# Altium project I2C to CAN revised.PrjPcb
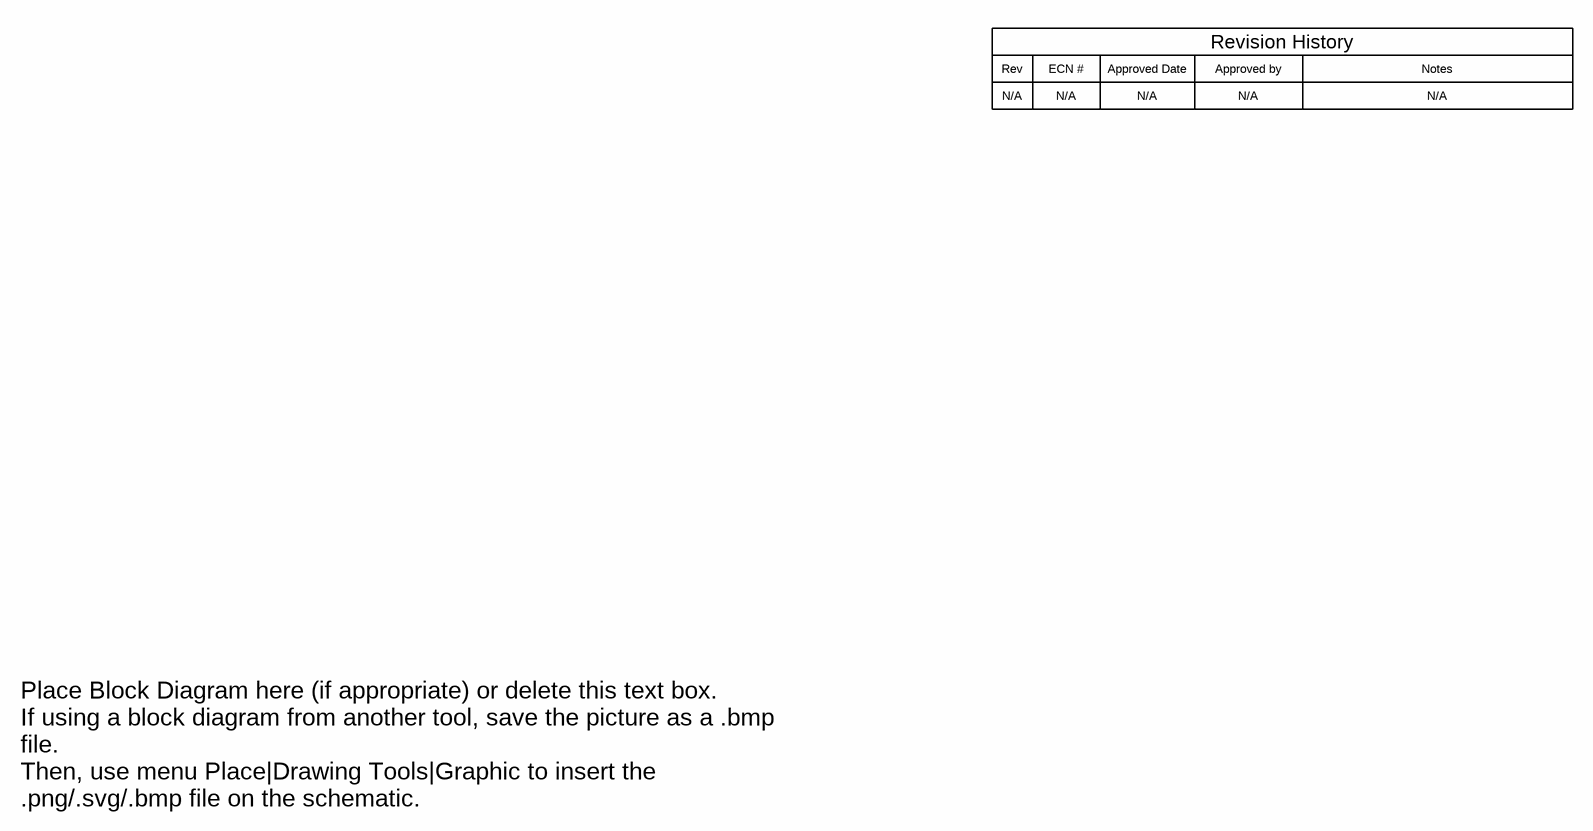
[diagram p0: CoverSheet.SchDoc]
CopyrightYear: 2017; PCB_Layout: Who did the Layout?; PCB_Rev: E1; PRJ_Customer: Public Release; PRJ_Engineer: Enter name of project lead; PRJ_Number: XX####; PRJ_Title: Change in menu Project|Project Options|Parameters; SCH_Rev: E1; TechSupport: http://www.ti.com/support; TID: N/A
3 sheets, 56 parts. Net scope: global (net labels, ports and power ports of the same name join across sheets).
Board file: I2C to CAN 2018.PcbDoc
Sheets:
  CoverSheet.SchDoc
  I2C to CAN 2018.SchDoc
  EVM_Hardware.SchDoc

## Sheet CoverSheet.SchDoc
size 431 x 279 mm; Date: Not shown in title block; ApprovedBy: Not shown in title block; CheckedBy: Not shown in title block; Author: Not shown in title block; CompanyName: Not shown in title block; Engineer: Not shown in title block; Organization: Not shown in title block; Address1: Not shown in title block; Address2: Not shown in title block; Address3: Not shown in title block; Address4: Not shown in title block; DocumentNumber: 1; Revision: Use project parameter SCH_Rev; SheetNumber: 1; SheetTotal: 3; PageSetup: Record=PageOptions¦CenterHorizontal=True¦CenterVertical=True¦PrintScale=1.00¦XCorrection=1.00¦YCorrection=1.00¦PrintKind=0¦BorderSize=5000000¦LeftOffset=0¦BottomOffset=0¦Orientation=2¦PaperLength=1000¦PaperWidth=1000¦Scale=100¦PaperSource=15¦PrintQuality=600¦MediaType=1¦DitherType=10¦PaperKind=Letter¦PrintScaleMode=1

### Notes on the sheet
- Rev
- N/A
- ECN #
- Approved Date
- Approved by
- Revision History
- Notes
- Place Block Diagram here (if appropriate) or delete this text box.
  If using a block diagram from another tool, save the picture as a .bmp file.
  Then, use menu Place|Drawing Tools|Graphic to insert the .png/.svg/.bmp file on the schematic.

## Sheet I2C to CAN 2018.SchDoc
size 431 x 279 mm; Date: Not shown in title block; ApprovedBy: Not shown in title block; CheckedBy: Not shown in title block; Author: Not shown in title block; CompanyName: Not shown in title block; Engineer: Not shown in title block; Organization: Not shown in title block; Address1: Not shown in title block; Address2: Not shown in title block; Address3: Not shown in title block; Address4: Not shown in title block; DocumentNumber: 1; Revision: Use project parameter SCH_Rev; SheetNumber: 2; SheetTotal: 3; PageSetup: Record=PageOptions¦CenterHorizontal=True¦CenterVertical=True¦PrintScale=1.00¦XCorrection=1.00¦YCorrection=1.00¦PrintKind=0¦BorderSize=5000000¦LeftOffset=0¦BottomOffset=0¦Orientation=2¦PaperLength=1000¦PaperWidth=1000¦Scale=100¦PaperSource=15¦PrintQuality=600¦MediaType=1¦DitherType=10¦PaperKind=Letter¦PrintScaleMode=1
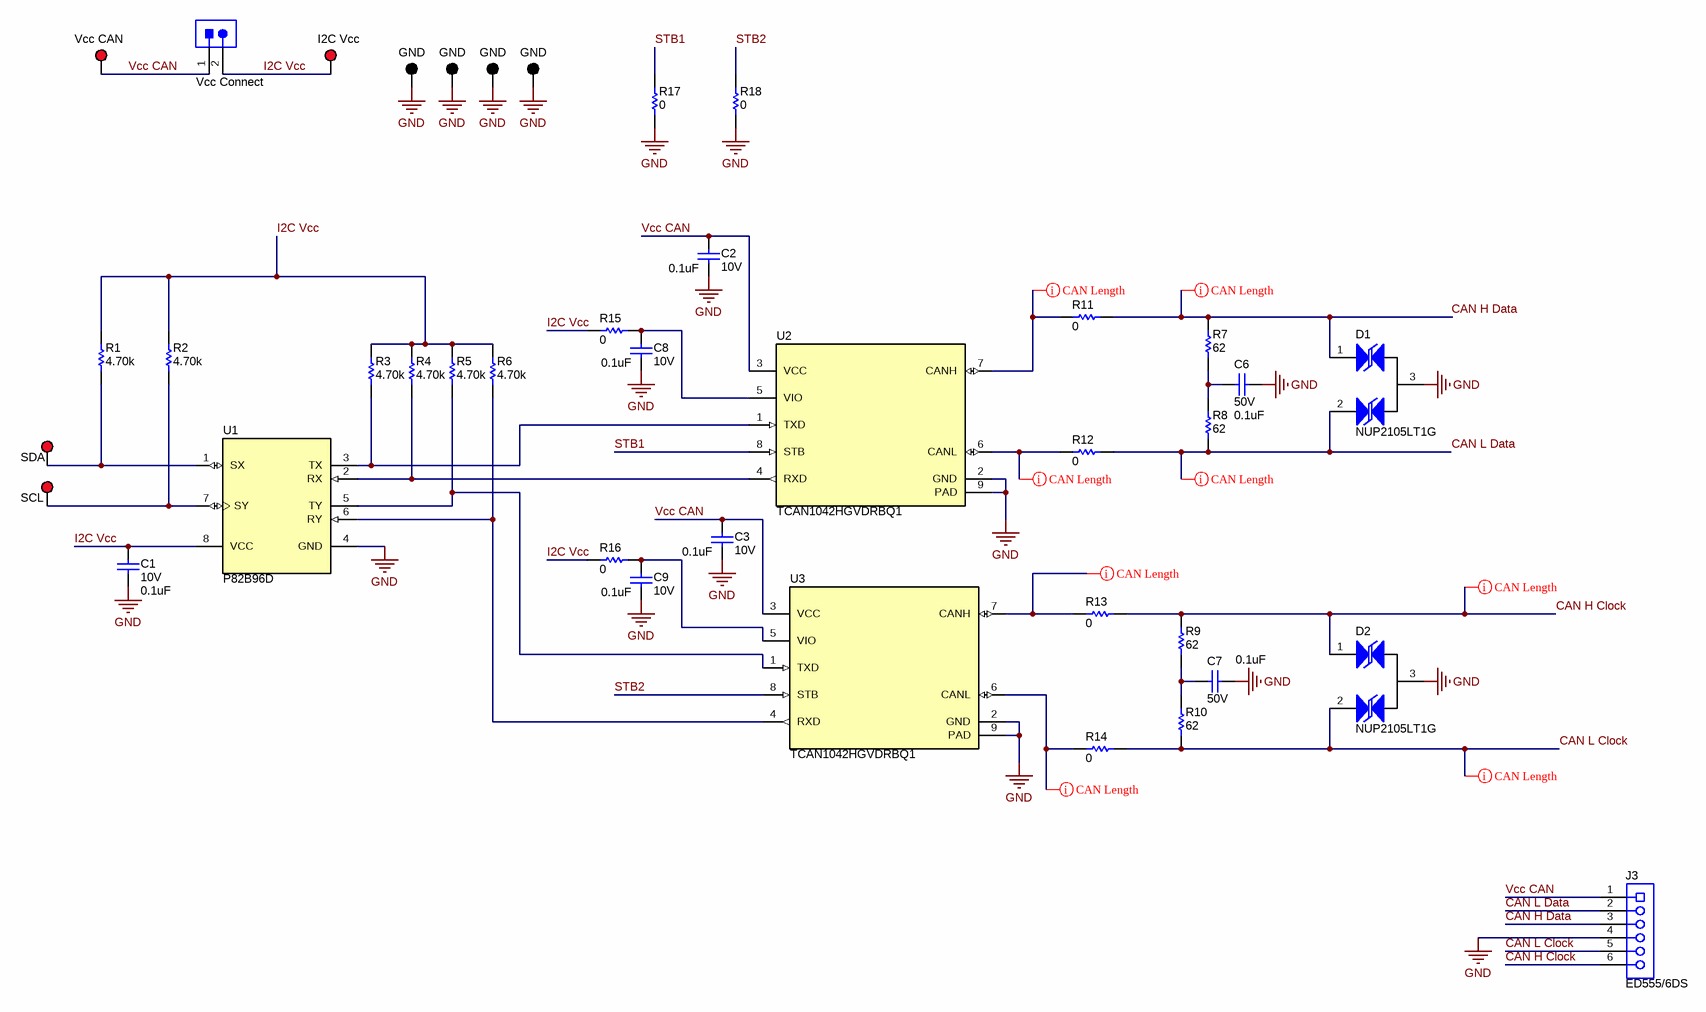
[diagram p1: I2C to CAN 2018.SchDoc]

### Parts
C1  VDC_V: 10V  ValueDisplayed: 0.1uF  [0603]  (hidden comment: 885012206020)
C2  VDC_V: 10V  ValueDisplayed: 0.1uF  [0603]  (hidden comment: 885012206020)
C3  VDC_V: 10V  ValueDisplayed: 0.1uF  [0603]  (hidden comment: 885012206020)
C6  VDC_V: 50V  ValueDisplayed: 0.1uF  [0603]  (hidden comment: C1608X5R1H104K080AA)
C7  VDC_V: 50V  ValueDisplayed: 0.1uF  [0603]  (hidden comment: C1608X5R1H104K080AA)
C8  VDC_V: 10V  ValueDisplayed: 0.1uF  [0603]  (hidden comment: 885012206020)
C9  VDC_V: 10V  ValueDisplayed: 0.1uF  [0603]  (hidden comment: 885012206020)
D1  NUP2105LT1G  [SOT-23]
D2  NUP2105LT1G  [SOT-23]
J3  ED555/6DS  [TERM_BLK_ED555-6DS]
J4  Vcc Connect  [3M_961102-6404-AR]
R1  ValueDisplayed: 4.70k  [0603]  (hidden comment: RT0603BRD074K7L)
R2  ValueDisplayed: 4.70k  [0603]  (hidden comment: RT0603BRD074K7L)
R3  ValueDisplayed: 4.70k  [0603]  (hidden comment: RT0603BRD074K7L)
R4  ValueDisplayed: 4.70k  [0603]  (hidden comment: RT0603BRD074K7L)
R5  ValueDisplayed: 4.70k  [0603]  (hidden comment: RT0603BRD074K7L)
R6  ValueDisplayed: 4.70k  [0603]  (hidden comment: RT0603BRD074K7L)
R7  ValueDisplayed: 62  [0603]  (hidden comment: CRCW060362R0JNEA)
R8  ValueDisplayed: 62  [0603]  (hidden comment: CRCW060362R0JNEA)
R9  ValueDisplayed: 62  [0603]  (hidden comment: CRCW060362R0JNEA)
R10  ValueDisplayed: 62  [0603]  (hidden comment: CRCW060362R0JNEA)
R11  ValueDisplayed: 0  [1210]  (hidden comment: CRCW12100000Z0EA)
R12  ValueDisplayed: 0  [1210]  (hidden comment: CRCW12100000Z0EA)
R13  ValueDisplayed: 0  [1210]  (hidden comment: CRCW12100000Z0EA)
R14  ValueDisplayed: 0  [1210]  (hidden comment: CRCW12100000Z0EA)
R15  ValueDisplayed: 0  [0603]  (hidden comment: RT0603BRD074K7L)
R16  ValueDisplayed: 0  [0603]  (hidden comment: RT0603BRD074K7L)
R17  ValueDisplayed: 0  [0603]  (hidden comment: RT0603BRD074K7L)
R18  ValueDisplayed: 0  [0603]  (hidden comment: RT0603BRD074K7L)
TP1  I2C Vcc  [Keystone5010]
TP2  Vcc CAN  [Keystone5010]
TP3  GND  [Keystone5011]
TP4  GND  [Keystone5011]
TP5  GND  [Keystone5011]
TP6  GND  [Keystone5011]
TP7  SDA  [Keystone5010]
TP8  SCL  [Keystone5010]
U1  P82B96D  [D0008A_L]
U2  TCAN1042HGVDRBQ1  [DRB0008F]
U3  TCAN1042HGVDRBQ1  [DRB0008F]

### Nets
GND: C1.2 C2.2 C3.2 C6.1 C7.1 C8.2 C9.2 D1.3 D2.3 J3.4 R17.1 R18.1 TP3.1 TP4.1 TP5.1 TP6.1 U1.4(GND) U2.2(GND) U2.9(PAD) U3.2(GND) U3.9(PAD)
CAN H Clock: D2.1 J3.6 R9.2 R13.1
CAN H Data: D1.1 J3.3 R7.2 R11.1
CAN L Clock: D2.2 J3.5 R10.1 R14.1
CAN L Data: D1.2 J3.2 R8.1 R12.1
I2C Vcc: C1.1 J4.2 R1.2 R2.2 R3.2 R4.2 R5.2 R6.2 R15.2 R16.2 TP1.1 U1.8(VCC)
STB1: R17.2 U2.8(STB)
STB2: R18.2 U3.8(STB)
Vcc CAN: C2.1 C3.1 J3.1 J4.1 TP2.1 U2.3(VCC) U3.3(VCC)
NetC6_2: C6.2 R7.1 R8.2
NetC7_2: C7.2 R9.1 R10.2
NetC8_1: C8.1 R15.1 U2.5(VIO)
NetC9_1: C9.1 R16.1 U3.5(VIO)
NetR1_1: R1.1 TP7.1 U1.1(SX)
NetR2_1: R2.1 TP8.1 U1.7(SY)
NetR3_1: R3.1 U1.3(TX) U2.1(TXD)
NetR4_1: R4.1 U1.2(RX) U2.4(RXD)
NetR5_1: R5.1 U1.5(TY) U3.1(TXD)
NetR6_1: R6.1 U1.6(RY) U3.4(RXD)
NetR11_2: R11.2 U2.7(CANH)
NetR12_2: R12.2 U2.6(CANL)
NetR13_2: R13.2 U3.7(CANH)
NetR14_2: R14.2 U3.6(CANL)

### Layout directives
net class Can Length 1: NetR11_2, NetR12_2, NetR13_2, NetR14_2
net class Can Length 2: CAN H Clock, CAN H Data, CAN L Clock, CAN L Data

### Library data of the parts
C1 = CMP-0064931-2: CAP, CERM, 0.1 uF, 10 V,+/- 10%, X7R, 0603; Manufacturer: Wurth Elektronik; TaMin_C: -55°C; Polarized: N; SizeAreaWB_mm2: 4.68; Value1: Unknown; U/M: EA; Value: 0.1uF; TaMax_C: 125°C; SizeZ_mm: 1; SizeX_mm: 1.6; SizeY_mm: 0.8; SizeArea_mm2: 1.28; Cap_F: 100nF; AEC Category: Q200
C2 C3 C8 C9 = CMP-0064931-2: CAP, CERM, 0.1 uF, 10 V,+/- 10%, X7R, 0603; Manufacturer: Wurth Elektronik; TaMin_C: -55°C; Polarized: N; SizeAreaWB_mm2: 4.68; Value1: Unknown; U/M: EA; Value: 0.1uF; TaMax_C: 125°C; SizeZ_mm: 1; SizeX_mm: 1.6; SizeY_mm: 0.8; SizeArea_mm2: 1.28; CompType: Capacitor; Cap_F: 100nF; AEC Category: Q200
C6 C7 = CMP-0007010-2: CAP, CERM, 0.1 uF, 50 V, +/- 10%, X5R, 0603; Manufacturer: TDK; TaMin_C: -55°C; ESR_ohm: 0.0296; Polarized: N; SizeAreaWB_mm2: 4.68; Value1: 0.0296 ohm; U/M: EA; Value: 0.1uF; TaMax_C: 85°C; SizeZ_mm: 1; SizeX_mm: 1.6; SizeY_mm: 0.8; SizeArea_mm2: 1.28; Cap_F: 100nF; IRMS_A: 9.7199dA; AEC Category: Q200
D1 D2 = CMP-0005919-2: Diode, TVS, Bi, 24 V, SOT-23; Manufacturer: ON Semiconductor; Power_W: 350mW; SizeAreaWB_mm2: 14; Vr_V: 24V; Value1: 0.35W; U/M: EA; Value: 24V; SizeZ_mm: 1.1; SizeX_mm: 2.5; SizeY_mm: 3; SizeArea_mm2: 7.5; AEC Category: Q101
J3 = ED555/6DS: Terminal Block, 3.5mm Pitch, 6x1, TH; Manufacturer: On-Shore Technology; SymbolCreator: a0411947; Pitch_mm: 3.5; Gender: Female; Shrouded: N; Row_Count: 1; ContactFinish: Brass; Current_A: 6; Voltage_V: 150; Cert_CULUS: Y; Green_Lifecycle: Not Set; Green_REACh: Incomplete
J4 = 961102-6404-AR: Header, 2.54mm, 2x1, TH; Manufacturer: 3M; SymbolCreator: a0412235; Pitch_mm: 2.54; Gender: Male; Shrouded: N; Row_Count: 1; ContactFinish: Gold; Current_A: 2; Voltage_V: 1000; Cert_UL: Y; Green_Lifecycle: Active; Green_REACh: Passed
R1-R6 R15-R18 = CMP-0024300-1: RES, 4.70 k, 0.1%, 0.1 W, 0603; Manufacturer: Yageo America; Power_W: 100mW; TempCo: 25 ppm/C; Value_Code: 4k70; U/M: EA; Value: 4.70k; EIA_Code: E192; Res_ohm: 4.7k; SizeX_mm: 1.6; SizeY_mm: 0.8; SizeZ_mm: 1; Value2: 0.1W; SizeArea_mm2: 1.28; VDC_V: 75V; AEC Category: Q200
R7-R10 = CMP-0025839-2: RES, 62, 5%, 0.1 W, 0603; Manufacturer: Vishay-Dale; Power_W: 100mW; TempCo: 200 ppm/C; Value_Code: 62R0; U/M: EA; Value: 62; EIA_Code: E24; SizeX_mm: 1.6; SizeY_mm: 0.8; SizeZ_mm: 1; Value2: 0.1W; SizeArea_mm2: 1.28; VDC_V: 75V; AEC Category: Q200
R11-R14 = CMP-0015016-2: RES, 0, 1%, 0.5 W, AEC-Q200 Grade 0, 1210; Manufacturer: Vishay-Dale; Power_W: 500mW; TempCo: ppm/C; SizeAreaWB_mm2: 14.7; U/M: EA; Value: 0; SizeX_mm: 3.2; SizeY_mm: 2.5; SizeZ_mm: 1.35; Value2: 0.5W; SizeArea_mm2: 8; AEC Qualified: Y; AEC Category: Q200
TP1 TP2 TP7 TP8 = 5010: Test Point, Multipurpose, Red, TH; Manufacturer: Keystone; CompType: Test Point Loop; ContactFinish: Silver; Green_Lifecycle: Active; Green_REACh: Passed
TP3-TP6 = 5011: Test Point, Multipurpose, Black, TH; Manufacturer: Keystone; CompType: Test Point Loop; ContactFinish: Silver; Green_Lifecycle: Active; Green_REACh: Passed
U1 = CMP-0043184-1: Dual Bidirectional Bus Buffer, 2 Channel Width, 2.0 to 15.0 V, -40 to 85 degC, 8-pin SOIC (D), Green (RoHS & no Sb/Br); Manufacturer: Texas Instruments; Open Drain I/O Type: Yes; Master Side I2C Bus Capacitance Supported(pF): 400; No. of Outputs: 2; SubFamily: I2C Hub, Buffer, Repeater; VCC(Max)(V): 15
U2 U3 = CMP-0065183-2: Automotive Fault Protected CAN Transceiver With Flexible Data-Rate, DRB0008F (VSON-8); Manufacturer: Texas Instruments; SizeX_mm: 3.0; CompType: IC; SizeZ_mm: 1.0; SizeArea_mm2: 9.0; SizeAreaWB_mm2: 16.0; U/M: EA

## Sheet EVM_Hardware.SchDoc
size 431 x 279 mm; Date: Not shown in title block; ApprovedBy: Not shown in title block; CheckedBy: Not shown in title block; Author: Not shown in title block; CompanyName: Not shown in title block; Engineer: Not shown in title block; Organization: Not shown in title block; Address1: Not shown in title block; Address2: Not shown in title block; Address3: Not shown in title block; Address4: Not shown in title block; DocumentNumber: 1; Revision: Use project parameter SCH_Rev; SheetNumber: 3; SheetTotal: 3; PageSetup: Record=PageOptions¦CenterHorizontal=True¦CenterVertical=True¦PrintScale=1.00¦XCorrection=1.00¦YCorrection=1.00¦PrintKind=0¦BorderSize=5000000¦LeftOffset=0¦BottomOffset=0¦Orientation=2¦PaperLength=1000¦PaperWidth=1000¦Scale=100¦PaperSource=15¦PrintQuality=600¦MediaType=1¦DitherType=10¦PaperKind=Letter¦PrintScaleMode=1
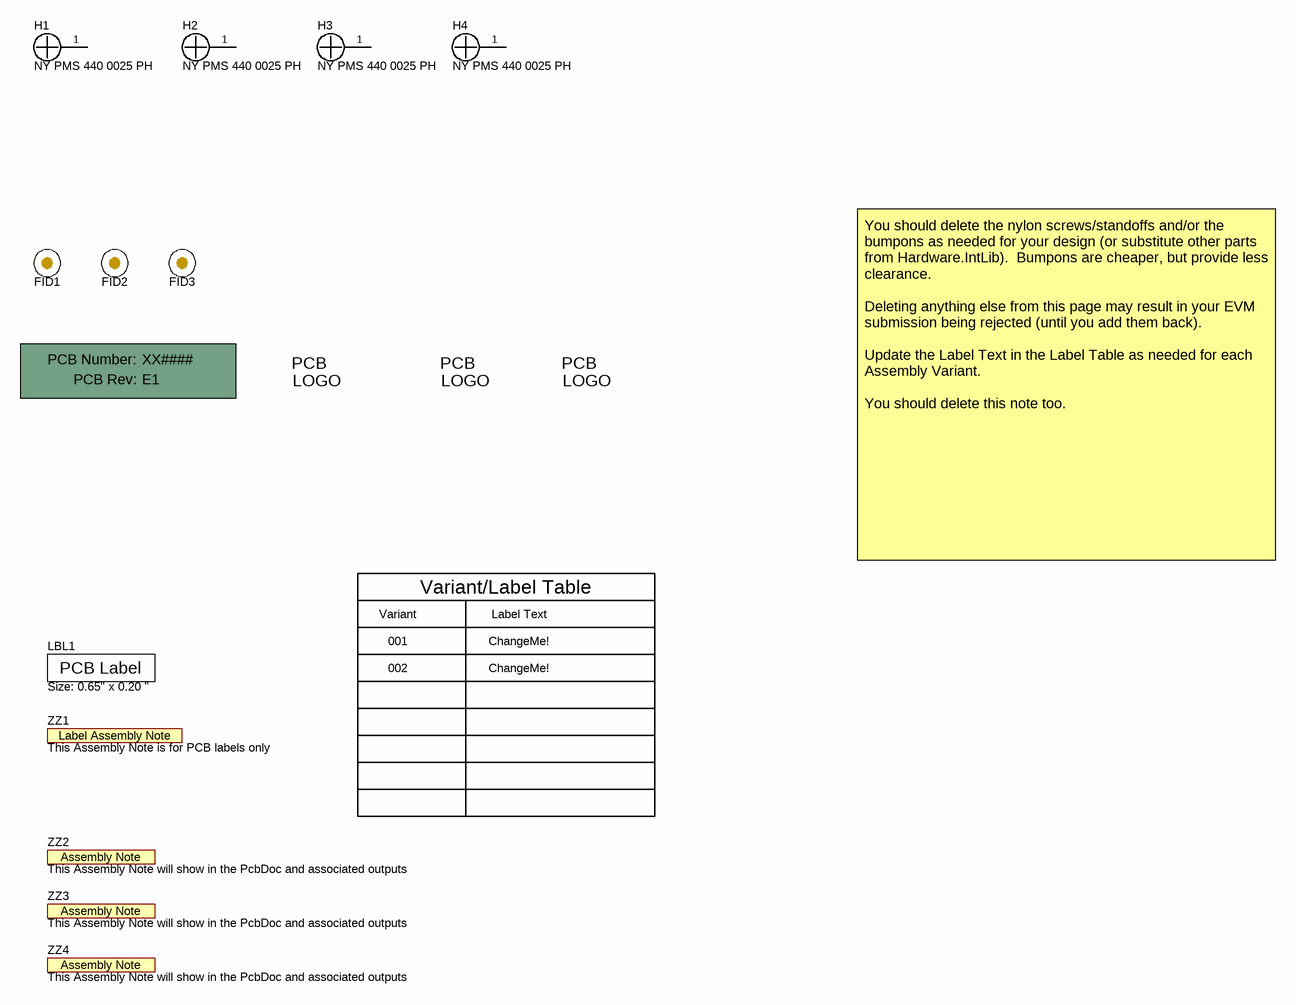
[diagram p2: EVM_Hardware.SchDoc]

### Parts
!PCB  Printed Circuit Board  (value not drawn)  (mechanical)
FID1  Fiducial  [Fiducial10-20]  (value not drawn)
FID2  Fiducial  [Fiducial10-20]  (value not drawn)
FID3  Fiducial  [Fiducial10-20]  (value not drawn)
H1  NY PMS 440 0025 PH  [NY PMS 440 0025 PH]
H2  NY PMS 440 0025 PH  [NY PMS 440 0025 PH]
H3  NY PMS 440 0025 PH  [NY PMS 440 0025 PH]
H4  NY PMS 440 0025 PH  [NY PMS 440 0025 PH]
LBL1  Size: 0.65" x 0.20 "  [Label_650x200]
Logo1  Texas Instruments  [TI_Stacked_Overlay_Small]  (value not drawn)  (no BOM)
Logo2  Pb-Free Symbol  [Pb-Free_Overlay_Small]  (value not drawn)  (no BOM)
Logo3  FCC disclaimer  [FCC_disclaimer]  (value not drawn)  (no BOM)
ZZ1  This Assembly Note is for PCB labels only  [AssemblyNoteLabel]  (no BOM)
ZZ2  This Assembly Note will show in the PcbDoc and associated outputs  [AssemblyNote]  (no BOM)
ZZ3  This Assembly Note will show in the PcbDoc and associated outputs  [AssemblyNote]  (no BOM)
ZZ4  This Assembly Note will show in the PcbDoc and associated outputs  [AssemblyNote]  (no BOM)

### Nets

Not connected (* = marked no-connect by the designer): H1 1; H2 1; H3 1; H4 1

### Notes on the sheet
- Variant
- Variant/Label Table
- Label Text
- You should delete the nylon screws/standoffs and/or the bumpons as needed for your design (or substitute other parts from Hardware.IntLib).  Bumpons are cheaper, but provide less clearance.
  Deleting anything else from this page may result in your EVM submission being rejected (until you add them back).
  Update the Label Text in the Label Table as needed for each Assembly Variant.
  You should delete this note too.
- 001
- 002
- ChangeMe!

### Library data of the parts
!PCB = PCB: Manufacturer: Any; PartNumber: XX####; SymbolCreator: a0412235
FID1-FID3 = Fiducial: Fiducial mark.  There is nothing to buy or mount.; SymbolCreator: codlsc
H1-H4 = NY PMS 440 0025 PH: Machine Screw, Round, #4-40 x 1/4, Nylon, Philips panhead; Manufacturer: B&F Fastener Supply; CompType: Hardware; SymbolCreator: codlsc; U/M: EA; Green_Lifecycle: Not Set; Green_REACh: Incomplete
LBL1 = THT-14-423-10: Thermal Transfer Printable Labels, 0.650" W x 0.200" H - 10,000 per roll; Manufacturer: Brady; SymbolCreator: a0412235; CompType: Label; Green_Lifecycle: Not Set; Green_REACh: Incomplete
Logo1 = TI_Logo: Texas Instrument Corporate Signature; SymbolCreator: a0412235
Logo2 = Pb-Free: SymbolCreator: a0412235
Logo3 = FCC_disclaimer: SymbolCreator: a0412235
ZZ1 = AssemblyNoteLabel: SymbolCreator: a0412235
ZZ2-ZZ4 = AssemblyNote: SymbolCreator: codlsc

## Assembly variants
001: not fitted FID1 FID2 FID3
